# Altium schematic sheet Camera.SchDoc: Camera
size A4; Date: Not used; ApprovedBy: Not used; CheckedBy: Not used; Author: Not used; CompanyName: STMicroelectronics; DrawnBy: Not used; Engineer: Not used; Organization: Not used; Address1: Not used; Address2: Not used; Address3: Not used; Address4: Not used; DocumentNumber: Not used; Revision: Not used; SheetNumber: 12; SheetTotal: 23
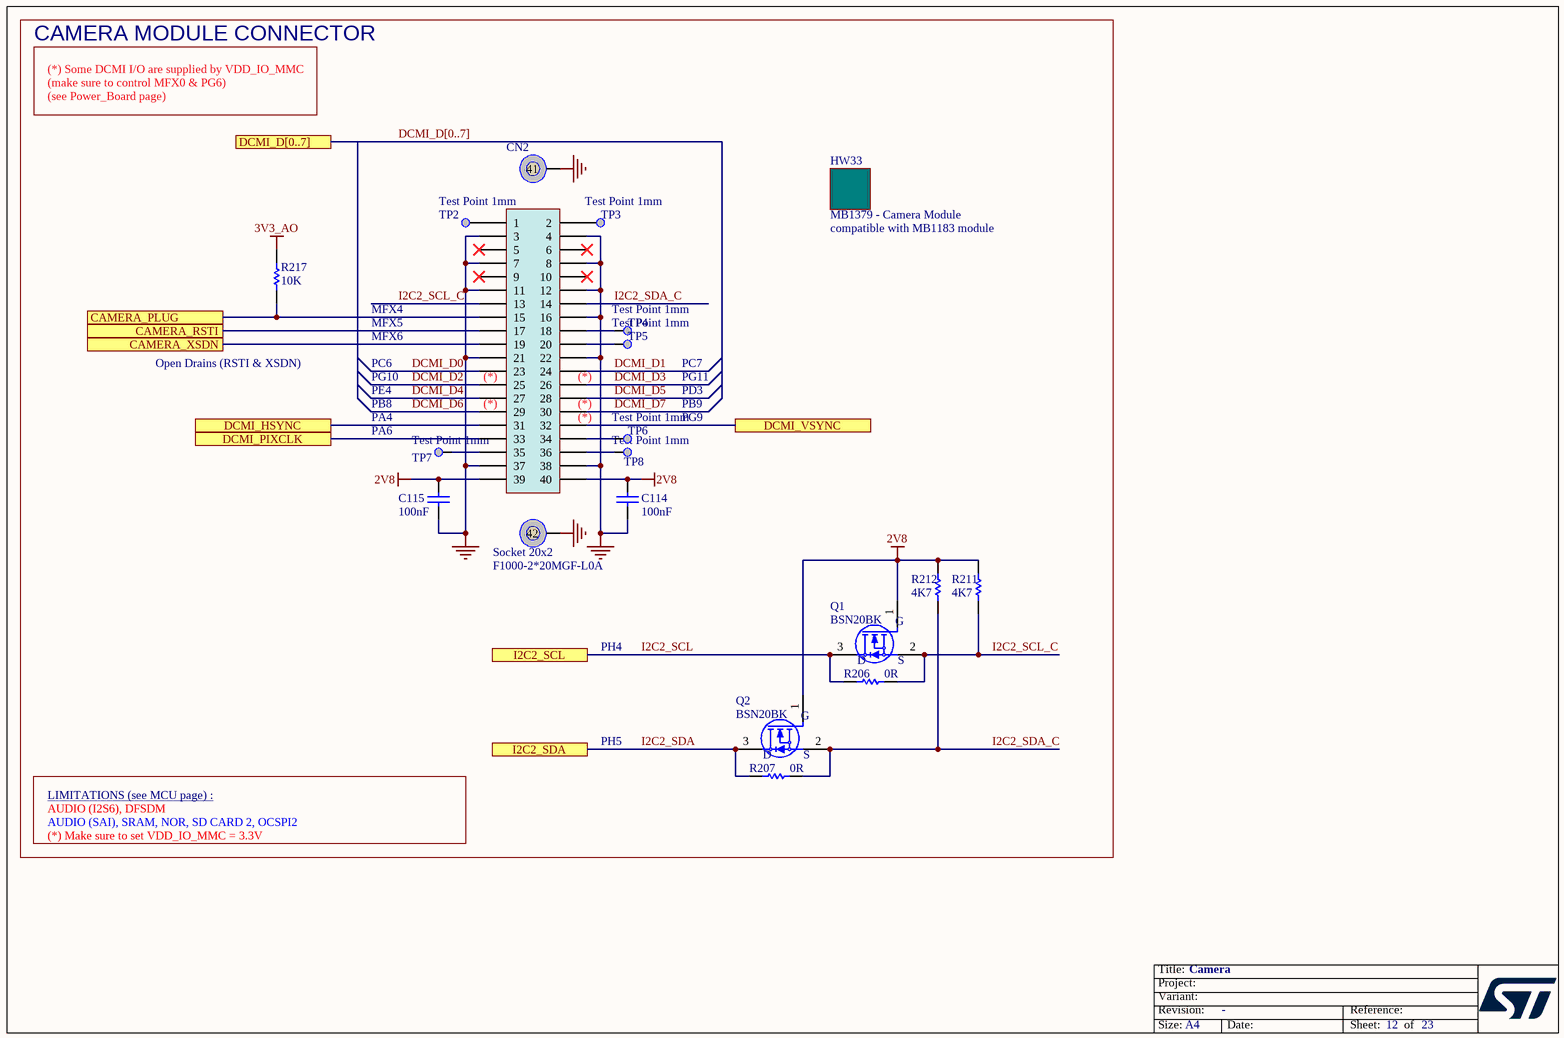
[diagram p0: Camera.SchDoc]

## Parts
C114  value 100nF  [C0402]  (hidden comment: Capacitor)
C115  value 100nF  [C0402]  (hidden comment: Capacitor)
CN2  value Socket 20x2  [CON_SAMTEC_CLM-120-02-L-D_Reverse-to-Camera]  (hidden comment: Socket 20x2 CLM_Reverse_for_camera)
HW33  value MB1379 - Camera Module  [MOD_CAMERA_MB1379]  (hidden comment: Daughter_Board)
Q1  value BSN20BK  [MOS_SOT23]  (hidden comment: BSN20)
Q2  value BSN20BK  [MOS_SOT23]  (hidden comment: BSN20)
R206  value 0R  [R0603]  (hidden comment: Resistor)
R207  value 0R  [R0603]  (hidden comment: Resistor)
R211  value 4K7  [R0402]  (hidden comment: Resistor)
R212  value 4K7  [R0402]  (hidden comment: Resistor)
R217  value 10K  [R0402]  (hidden comment: Resistor)
TP2  value Test Point 1mm  [TP_SMD_1MM]  (hidden comment: Test Point)  (no BOM)
TP3  value Test Point 1mm  [TP_SMD_1MM]  (hidden comment: Test Point)  (no BOM)
TP4  value Test Point 1mm  [TP_SMD_1MM]  (hidden comment: Test Point)  (no BOM)
TP5  value Test Point 1mm  [TP_SMD_1MM]  (hidden comment: Test Point)  (no BOM)
TP6  value Test Point 1mm  [TP_SMD_1MM]  (hidden comment: Test Point)  (no BOM)
TP7  value Test Point 1mm  [TP_SMD_1MM]  (hidden comment: Test Point)  (no BOM)
TP8  value Test Point 1mm  [TP_SMD_1MM]  (hidden comment: Test Point)  (no BOM)

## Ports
CAMERA_PLUG, CAMERA_RSTI, CAMERA_XSDN, DCMI_D[0..7], DCMI_HSYNC, DCMI_PIXCLK, DCMI_VSYNC, I2C2_SCL, I2C2_SDA

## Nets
2V8: C114.2 C115.2 CN2.39 CN2.40 Q1.1(G) Q2.1(G) R211.2 R212.2
3V3_AO: R217.2
GND: C114.1 C115.1 CN2.3 CN2.4 CN2.7 CN2.8 CN2.11 CN2.12 CN2.16 CN2.21 CN2.22 CN2.37 CN2.38 CN2.41 CN2.42
CAMERA_PLUG: CN2.15 R217.1 ; port CAMERA_PLUG
CAMERA_RSTI: CN2.17 ; port CAMERA_RSTI
CAMERA_XSDN: CN2.19 ; port CAMERA_XSDN
DCMI_D0: CN2.23
DCMI_D1: CN2.24
DCMI_D2: CN2.25
DCMI_D3: CN2.26
DCMI_D4: CN2.27
DCMI_D5: CN2.28
DCMI_D6: CN2.29
DCMI_D7: CN2.30
DCMI_HSYNC: CN2.31 ; port DCMI_HSYNC
DCMI_PIXCLK: CN2.33 ; port DCMI_PIXCLK
DCMI_VSYNC: CN2.32 ; port DCMI_VSYNC
I2C2_SCL: Q1.3(D) R206.1 ; port I2C2_SCL
I2C2_SCL_C: CN2.13 Q1.2(S) R206.2 R211.1
I2C2_SDA: Q2.3(D) R207.1 ; port I2C2_SDA
I2C2_SDA_C: CN2.14 Q2.2(S) R207.2 R212.1
NetCN2_1: CN2.1 TP2.1
NetCN2_2: CN2.2 TP3.1
NetCN2_18: CN2.18 TP4.1
NetCN2_20: CN2.20 TP5.1
NetCN2_34: CN2.34 TP6.1
NetCN2_35: CN2.35 TP7.1
NetCN2_36: CN2.36 TP8.1

Not connected (* = marked no-connect by the designer): CN2 5* 6* 9* 10*

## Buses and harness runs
bus DCMI_D[0..7] = port DCMI_D[0..7]

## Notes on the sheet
- CAMERA MODULE CONNECTOR
- (*) Some DCMI I/O are supplied by VDD_IO_MMC
  (make sure to control MFX0 & PG6)
  (see Power_Board page)
- compatible with MB1183 module
- MFX4
- Open Drains (RSTI & XSDN)
- PC6
- PG10
- MFX5
- MFX6
- (near CN2) (*)
- PC7
- PG11
- PE4
- PB8
- PA4
- PA6
- PB9
- PG9
- PD3
- (near CN2) F1000-2*20MGF-L0A
- PH4
- PH5
- LIMITATIONS (see MCU page) :
- AUDIO (SAI), SRAM, NOR, SD CARD 2, OCSPI2
- AUDIO (I2S6), DFSDM
- (*) Make sure to set VDD_IO_MMC = 3.3V

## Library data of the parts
C114 C115 = MCD-00006: Capacitor, MLCC, 100nF, 16V, X7R, 10%, 0402, T=0.5mm; Manufacturer_Part_Number: CC0402KRX7R7BB104; Manufacturer: YAGEO; Alternate_Manufacturer_Part_Number: GCM155R71C104KA55D; Alternate_Manufacturer: MURATA; Part_Preference: Recommended; Partial_Alternate_Internal_Part_Number: MCD-03299; Provided_By: SUBCO; ECCN_US: EAR99; ECCN_EU: NEC; Component_Country_Of_Origin: China; ID: 2474; Order_Code_RS: 9402047; ShowFields: YES
CN2 = MCD-00138: Socket, 20x2, 1.0mm, VR, SMT, Height 2.26mm. Symbol & Footprint dedicated to MB1183 & MB1379 camera modules (not in line with Samtec datasheet); Part_Type: Connector; Manufacturer_Part_Number: CLM-120-02-L-D; Part_Preference: Recommended; Provided_By: SUBCO; ECCN_US: EAR99; ECCN_EU: NEC; Component_Country_Of_Origin: China, Costa Rica, Malaysia, USA, Vietnam; ID: 2727; Order_Code_RS: 766-8748; ShowFields: YES
HW33 = MCD-01034: Camera Module(to replace MB1183 module); Part_Type: Misc; Manufacturer: STMICROELECTRONICS; BMS_Part_Number: MB1379; Part_Preference: Recommended; Provided_By: SUBCO with ST control; Component_Country_Of_Origin: Unknown; ID: 2985; ShowFields: YES
Q1 Q2 = MCD-01969: N-channel enhancement mode field-effect transistor; Manufacturer: Nexperia; Part_Preference: Recommended; ECCN_US: EAR99; ECCN_EU: NEC; Provided_By: SUBCO; Component_Country_Of_Origin: China; ID: 4069; Order_Code_RS: 136-4845; ShowFields: YES
R206 R207 = MCD-00056: Resistor,0R,0603,5%,1/10W; Manufacturer_Part_Number: RC0603JR-070RL; Manufacturer: YAGEO; Part_Preference: Recommended; Provided_By: SUBCO; ECCN_US: EAR99; ECCN_EU: NEC; Component_Country_Of_Origin: China; ID: 2536; Order_Code_RS: 9233130RL; ShowFields: YES
R211 R212 = MCD-00065: Resistor,4K7,0402,1%,1/16W; Manufacturer_Part_Number: RC0402FR-074K7L; Manufacturer: YAGEO; Alternate_Manufacturer_Part_Number: RT0402FRE074K7L; Part_Preference: Recommended; Partial_Alternate_Internal_Part_Number: MCD-03300; Provided_By: SUBCO; ECCN_US: EAR99; ECCN_EU: NEC; Component_Country_Of_Origin: China; ID: 2526; Order_Code_RS: 9239316; ShowFields: YES
R217 = MCD-00053: Resistor,10K,0402,1%,1/16W; Manufacturer_Part_Number: RC0402FR-0710KL; Manufacturer: YAGEO; BMS_Part_Number: 9131590; Part_Preference: Recommended; Provided_By: SUBCO; ECCN_US: EAR99; ECCN_EU: NEC; Component_Country_Of_Origin: China; ID: 2539; Order_Code_RS: 9239359; ShowFields: YES
TP2-TP8 = MCD-00074: Test Point 1mm; Part_Type: Misc; Part_Preference: Recommended; Component_Country_Of_Origin: Unknown; ID: 2518; ShowFields: YES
